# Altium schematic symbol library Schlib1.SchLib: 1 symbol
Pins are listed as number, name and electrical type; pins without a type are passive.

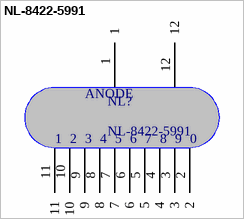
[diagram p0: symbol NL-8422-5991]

## NL-8422-5991
designator NL?
NL-8422-5991 Nixie Tube
footprint PCBComponent_1
pins: 1, 2, 3, 4, 5, 6, 7, 8, 9, 10, 11, 12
